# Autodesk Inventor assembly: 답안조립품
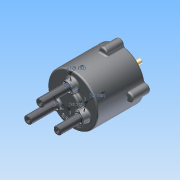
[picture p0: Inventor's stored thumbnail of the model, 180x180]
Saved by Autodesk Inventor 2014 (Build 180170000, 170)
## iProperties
Created: 2015-09
Part Number: 답안조립품
Document SubType Name: Assembly
Designer: study
Author: study
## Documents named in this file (14)
- C:\Users\study\Desktop\350916V1016\답안조립품.iam
- C:\Users\study\Desktop\350916V1016\몸체.ipt
- C:\Users\study\Desktop\350916V1016\M5x0.8x20.ipt
- C:\Users\study\Desktop\350916V1016\오일실.ipt
- C:\Users\study\Desktop\350916V1016\커버.ipt
- C:\Users\study\Desktop\350916V1016\메인 축.ipt
- C:\Users\study\Desktop\350916V1016\멈춤링 22 x 1.2.ipt
- C:\Users\study\Desktop\350916V1016\베어링 NA 4900.ipt
- C:\Users\study\Desktop\350916V1016\판캠.ipt
- C:\Users\study\Desktop\350916V1016\슬라이드 축.ipt
- C:\Users\study\Desktop\350916V1016\멈춤링 10 x 1.ipt
- C:\Users\study\Desktop\350916V1016\11-가변스프링.ipt
- C:\Users\study\Desktop\350916V1016\12-가변스프링.ipt
- C:\Users\study\Desktop\350916V1016\13-가변스프링.ipt
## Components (7 placed, 4 different names)
1. 11-가변스프링:1
2. 12-가변스프링:1
3. 13-가변스프링:1
4. M5x0.8x20:1
5. M5x0.8x20:2
6. M5x0.8x20:3
7. M5x0.8x20:4
